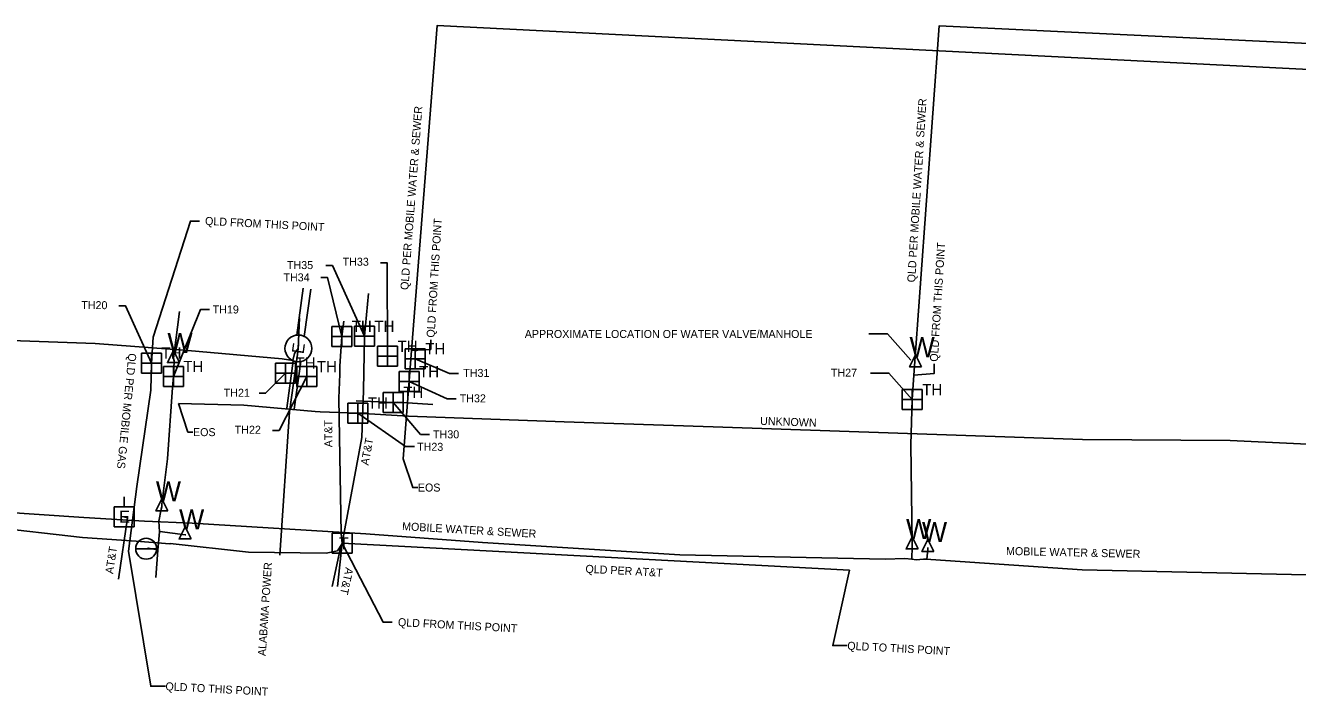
# Model space of a CAD drawing. Extents: x 1797765 to 1816938, y 246120 to 250965.
# Drawn here: x 1798766.8 to 1799084.8, y 248819.2 to 248986.7 of the extents above; entities that cross this region are included whole.
import ezdxf

# ---------------------------------------------------------------- set-up
doc = ezdxf.new("R2010")
doc.units = 0
for name, color, linetype in [('EX-OHUT-ELEC', 7, 'Continuous'), ('EX-UGUT-ELEC', 7, 'Continuous'), ('EX-UGUT-ELEC-X-CARDNO-X', 7, 'Continuous'), ('EX-UGUT-FOC-X-CARDNO-X', 7, 'Continuous'), ('EX-UGUT-GAS_MAIN-X-CARDNO-X', 7, 'Continuous'), ('EX-UGUT-PHONE', 7, 'Continuous'), ('EX-UGUT-TXT', 7, 'Continuous'), ('EX-UGUT-WATER', 7, 'Continuous'), ('EX-UGUT-WATER-X-CARDNO-X', 7, 'Continuous'), ('EX-UGUT-X-CARDNO-X', 7, 'Continuous'), ('SU_QLATestHole_ep', 7, 'Continuous'), ('UG-BURIED SANITARY SEWER', 7, 'Continuous'), ('UGUT-TXT', 7, 'Continuous')]:
    doc.layers.add(name, color=color, linetype=linetype)

msp = doc.modelspace()

# ---------------------------------------------------------------- linework, layer by layer
at = {"layer": 'EX-OHUT-ELEC'}
for p, q in [((1798791.5, 248868.94), (1798791.5, 248866.44)), ((1798789, 248866.44), (1798789, 248861.44)), ((1798794, 248861.44), (1798794, 248866.44)), ((1798789, 248861.44), (1798794, 248861.44))]:
    msp.add_line(p, q, dxfattribs=at)
msp.add_lwpolyline([(1798794, 248866.44), (1798791.5, 248866.44), (1798789, 248866.44)], dxfattribs=at)
at = {"layer": 'EX-UGUT-ELEC'}
for p, q in [((1798834.61, 248909.32), (1798836.23, 248921.06)), ((1798836.48, 248909.01), (1798838.11, 248920.8)), ((1798833.73, 248902.9), (1798832.11, 248891.11)), ((1798835.62, 248902.71), (1798833.99, 248890.85))]:
    msp.add_line(p, q, dxfattribs=at)
msp.add_circle((1798835.01, 248906), 3.35, dxfattribs=at)
at = {"layer": 'EX-UGUT-ELEC-X-CARDNO-X'}
for points in [[(1798735.14, 248908.97), (1798784.23, 248907.21), (1798807.35, 248905.49), (1798831, 248903.38), (1798833.59, 248902.99), (1798834.03, 248904.75), (1798834.95, 248906), (1798835.06, 248907.8), (1798835.33, 248913.62)], [(1798830.37, 248854.33), (1798832.78, 248890.14), (1798834.77, 248904.45), (1798834.95, 248906)]]:
    msp.add_lwpolyline(points, dxfattribs=at)
at = {"layer": 'EX-UGUT-FOC-X-CARDNO-X'}
msp.add_line((1798845.98, 248857.32), (1798972.76, 248850.58), dxfattribs=at)
for points in [[(1798844.81, 248846.5), (1798845.98, 248857.32), (1798850.89, 248883.71), (1798851.27, 248895.5), (1798851.53, 248909.03), (1798852.54, 248919.76)], [(1798845.98, 248857.32), (1798845.72, 248859.62), (1798845.15, 248893.61), (1798845.37, 248899.55), (1798845.4, 248901.59), (1798845.86, 248909.01), (1798846.34, 248912.82)], [(1798452.8, 248869.31), (1798454.41, 248875.69), (1798456.91, 248875.31), (1798485.69, 248873.18), (1798536.5, 248869.69), (1798574.45, 248870.48), (1798588.78, 248870.53), (1798685, 248864.35), (1798734.11, 248864.07), (1798781.01, 248858.73), (1798794.5, 248857.79), (1798802.91, 248857.14), (1798802.96, 248857.22), (1798822.56, 248855.06), (1798841.97, 248854.84), (1798844.79, 248855.44), (1798846.01, 248857.33), (1798845.98, 248857.32)], [(1798790.05, 248848.31), (1798792.3, 248863.69), (1798791.5, 248863.94)], [(1798845.98, 248857.32), (1798845.38, 248855.37), (1798843.49, 248846.47)]]:
    msp.add_lwpolyline(points, dxfattribs=at)
at = {"layer": 'EX-UGUT-GAS_MAIN-X-CARDNO-X'}
msp.add_lwpolyline([(1798792.53, 248855.29), (1798794.61, 248871.47), (1798798.13, 248895.56), (1798798.29, 248902.34), (1798798.73, 248908.82)], dxfattribs=at)
at = {"layer": 'EX-UGUT-PHONE'}
for p, q in [((1798848.48, 248859.82), (1798843.48, 248859.82)), ((1798843.48, 248859.82), (1798843.48, 248854.82)), ((1798848.48, 248854.82), (1798848.48, 248859.82)), ((1798843.48, 248854.82), (1798848.48, 248854.82))]:
    msp.add_line(p, q, dxfattribs=at)
at = {"layer": 'EX-UGUT-TXT'}
for points in [[(1798810.26, 248937.84), (1798808.01, 248937.84), (1798798.73, 248908.82)], [(1798841.9, 248926.74), (1798843.54, 248926.74), (1798851.53, 248909.03)], [(1798855.53, 248927.42), (1798857.17, 248927.42), (1798857.32, 248904.03)], [(1798840.65, 248923.77), (1798842.29, 248923.77), (1798845.86, 248909.01)], [(1798790.15, 248916.63), (1798791.8, 248916.63), (1798798.29, 248902.34)], [(1798812.83, 248915.76), (1798810.57, 248915.76), (1798803.76, 248899)], [(1798977.66, 248909.64), (1798982.25, 248909.64), (1798988.08, 248903.03)], [(1798868.11, 248908.17), (1798868.11, 248905.74), (1798863.32, 248905.48)], [(1798875.08, 248899.73), (1798872.82, 248899.73), (1798864.21, 248903.42)], [(1798825.17, 248894.79), (1798826.81, 248894.79), (1798831.81, 248899.85)], [(1798978.05, 248899.83), (1798982.64, 248899.83), (1798988.47, 248893.22)], [(1798993.93, 248902.13), (1798993.93, 248899.71), (1798988.9, 248899.32)], [(1798828.54, 248885.5), (1798830.19, 248885.5), (1798837.14, 248898.95)], [(1798874.48, 248893.42), (1798872.22, 248893.42), (1798862.69, 248897.7)], [(1798808.67, 248885.08), (1798807.39, 248885.08), (1798805.02, 248892.23)], [(1798867.81, 248884.53), (1798865.55, 248884.53), (1798858.73, 248892.53)], [(1798864.06, 248881.47), (1798861.8, 248881.47), (1798849.89, 248889.84)], [(1798864.88, 248871.23), (1798863.6, 248871.23), (1798861.24, 248878.38)], [(1798801.79, 248821.56), (1798798.12, 248821.56), (1798792.53, 248855.29)], [(1798858.49, 248837.55), (1798856.23, 248837.55), (1798845.98, 248857.32)], [(1798972.24, 248831.72), (1798968.58, 248831.72), (1798972.76, 248850.58)]]:
    msp.add_lwpolyline(points, dxfattribs=at)
at = {"layer": 'EX-UGUT-WATER'}
for p, q in [((1798805.27, 248902.45), (1798803.77, 248905.45)), ((1798990.8, 248901.4), (1798989.3, 248904.4)), ((1798802.38, 248865.4), (1798800.88, 248868.4)), ((1798808.19, 248858.37), (1798806.69, 248861.37)), ((1798989.94, 248855.91), (1798988.44, 248858.91)), ((1798993.9, 248855.23), (1798992.4, 248858.23)), ((1798794.33, 248855.94), (1798799.58, 248855.94))]:
    msp.add_line(p, q, dxfattribs=at)
for points in [[(1798803.77, 248905.45), (1798802.27, 248902.45), (1798805.27, 248902.45)], [(1798989.3, 248904.4), (1798987.8, 248901.4), (1798990.8, 248901.4)], [(1798800.88, 248868.4), (1798799.38, 248865.4), (1798802.38, 248865.4)], [(1798806.69, 248861.37), (1798805.19, 248858.37), (1798808.19, 248858.37)], [(1798988.44, 248858.91), (1798986.94, 248855.91), (1798989.94, 248855.91)], [(1798992.4, 248858.23), (1798990.9, 248855.23), (1798993.9, 248855.23)]]:
    msp.add_lwpolyline(points, dxfattribs=at)
msp.add_circle((1798796.96, 248855.94), 2.62, dxfattribs=at)
at = {"layer": 'EX-UGUT-WATER-X-CARDNO-X'}
for points in [[(1798988.9, 248899.32), (1798995.21, 248986.66), (1799521.08, 248961.5)], [(1798805.28, 248915.24), (1798803.9, 248904.18), (1798803.77, 248903.45), (1798803.95, 248902.9), (1798803.76, 248899), (1798803.57, 248896.25), (1798802.31, 248878.44), (1798800.88, 248867.11), (1798800.88, 248866.4), (1798800.72, 248865.81), (1798800.14, 248862.82), (1798800.29, 248860.2), (1798799.85, 248855.55), (1798799.36, 248848.73)], [(1798988.34, 248853.31), (1798988.47, 248856.53), (1798988.44, 248856.91), (1798988.48, 248857.39), (1798988.08, 248882.02), (1798988.47, 248893.22), (1798988.9, 248899.32)], [(1798685.79, 248870.12), (1798781.34, 248863.77), (1798796.52, 248862.81), (1798808.44, 248862.33), (1798851.84, 248859.62), (1798881.05, 248857.49), (1798930.39, 248854.37), (1798981.68, 248853.31), (1798986.59, 248853.5), (1798988.34, 248853.31), (1798989.48, 248853.2), (1798991.29, 248853.29), (1798992.11, 248853.31), (1798993.09, 248853.22), (1799030.93, 248850.68), (1799131.89, 248848.4)], [(1798800.29, 248860.2), (1798800.36, 248860.21), (1798806.69, 248859.37), (1798806.92, 248859.4)], [(1798799.85, 248855.56), (1798799.71, 248855.65), (1798797.52, 248856.07), (1798796.96, 248855.94)], [(1798992.11, 248853.31), (1798992.4, 248855.74), (1798992.4, 248856.23)]]:
    msp.add_lwpolyline(points, dxfattribs=at)
at = {"layer": 'EX-UGUT-X-CARDNO-X'}
for points in [[(1798805.02, 248892.23), (1798821.39, 248891.83), (1798839.2, 248890.25), (1798840.43, 248890.19), (1798849.89, 248889.84), (1798862.58, 248889.1), (1798901.44, 248887.68), (1798938.68, 248886.37), (1799031.01, 248883.21), (1799067.99, 248882.95), (1799152.4, 248879.01)], [(1798849.43, 248892.91), (1798858.73, 248892.53), (1798859.74, 248892.58), (1798868.62, 248891.95)]]:
    msp.add_lwpolyline(points, dxfattribs=at)
at = {"layer": 'SU_QLATestHole_ep'}
for p, q in [((1798843.36, 248911.51), (1798848.36, 248911.51)), ((1798843.36, 248906.51), (1798843.36, 248911.51)), ((1798843.36, 248911.51), (1798843.36, 248909.01)), ((1798845.86, 248911.51), (1798843.36, 248911.51)), ((1798843.36, 248909.01), (1798848.36, 248909.01)), ((1798843.36, 248909.01), (1798845.86, 248909.01)), ((1798845.86, 248911.51), (1798845.86, 248906.51)), ((1798845.86, 248909.01), (1798845.86, 248911.51)), ((1798848.36, 248909.01), (1798845.86, 248909.01)), ((1798845.86, 248909.01), (1798845.86, 248906.51)), ((1798848.36, 248911.51), (1798848.36, 248906.51)), ((1798848.36, 248906.51), (1798848.36, 248909.01)), ((1798849.03, 248911.53), (1798854.03, 248911.53)), ((1798849.03, 248906.53), (1798849.03, 248911.53)), ((1798849.03, 248911.53), (1798849.03, 248909.03)), ((1798851.53, 248911.53), (1798849.03, 248911.53)), ((1798849.03, 248909.03), (1798854.03, 248909.03)), ((1798849.03, 248909.03), (1798851.53, 248909.03)), ((1798851.53, 248911.53), (1798851.53, 248906.53)), ((1798851.53, 248909.03), (1798851.53, 248911.53)), ((1798854.03, 248909.03), (1798851.53, 248909.03)), ((1798851.53, 248909.03), (1798851.53, 248906.53)), ((1798854.03, 248911.53), (1798854.03, 248906.53)), ((1798854.03, 248906.53), (1798854.03, 248909.03)), ((1798848.36, 248906.51), (1798843.36, 248906.51)), ((1798845.86, 248906.51), (1798848.36, 248906.51)), ((1798854.03, 248906.53), (1798849.03, 248906.53)), ((1798851.53, 248906.53), (1798854.03, 248906.53)), ((1798854.82, 248906.53), (1798859.82, 248906.53)), ((1798854.82, 248901.53), (1798854.82, 248906.53)), ((1798854.82, 248906.53), (1798854.82, 248904.03)), ((1798857.32, 248906.53), (1798854.82, 248906.53)), ((1798857.32, 248906.53), (1798857.32, 248901.53)), ((1798857.32, 248904.03), (1798857.32, 248906.53)), ((1798859.82, 248906.53), (1798859.82, 248901.53)), ((1798861.71, 248905.92), (1798866.71, 248905.92)), ((1798861.71, 248900.92), (1798861.71, 248905.92)), ((1798861.71, 248905.92), (1798861.71, 248903.42)), ((1798864.21, 248905.92), (1798861.71, 248905.92)), ((1798864.21, 248905.92), (1798864.21, 248900.92)), ((1798864.21, 248903.42), (1798864.21, 248905.92)), ((1798866.71, 248905.92), (1798866.71, 248900.92)), ((1798795.79, 248904.84), (1798800.79, 248904.84)), ((1798795.79, 248899.84), (1798795.79, 248904.84)), ((1798795.79, 248904.84), (1798795.79, 248902.34)), ((1798798.29, 248904.84), (1798795.79, 248904.84)), ((1798798.29, 248904.84), (1798798.29, 248899.84)), ((1798798.29, 248902.34), (1798798.29, 248904.84)), ((1798800.79, 248904.84), (1798800.79, 248899.84)), ((1798854.82, 248904.03), (1798859.82, 248904.03)), ((1798854.82, 248904.03), (1798857.32, 248904.03)), ((1798859.82, 248904.03), (1798857.32, 248904.03)), ((1798857.32, 248904.03), (1798857.32, 248901.53)), ((1798859.82, 248901.53), (1798859.82, 248904.03)), ((1798861.71, 248903.42), (1798866.71, 248903.42)), ((1798861.71, 248903.42), (1798864.21, 248903.42)), ((1798866.71, 248903.42), (1798864.21, 248903.42)), ((1798864.21, 248903.42), (1798864.21, 248900.92)), ((1798866.71, 248900.92), (1798866.71, 248903.42)), ((1798795.79, 248902.34), (1798800.79, 248902.34)), ((1798795.79, 248902.34), (1798798.29, 248902.34)), ((1798800.79, 248899.84), (1798795.79, 248899.84)), ((1798800.79, 248902.34), (1798798.29, 248902.34)), ((1798798.29, 248902.34), (1798798.29, 248899.84)), ((1798798.29, 248899.84), (1798800.79, 248899.84)), ((1798800.79, 248899.84), (1798800.79, 248902.34)), ((1798801.26, 248901.5), (1798806.26, 248901.5)), ((1798801.26, 248896.5), (1798801.26, 248901.5)), ((1798801.26, 248901.5), (1798801.26, 248899)), ((1798803.76, 248901.5), (1798801.26, 248901.5)), ((1798803.76, 248901.5), (1798803.76, 248896.5)), ((1798803.76, 248899), (1798803.76, 248901.5)), ((1798806.26, 248901.5), (1798806.26, 248896.5)), ((1798829.31, 248902.35), (1798834.31, 248902.35)), ((1798829.31, 248897.35), (1798829.31, 248902.35)), ((1798829.31, 248902.35), (1798829.31, 248899.85)), ((1798831.81, 248902.35), (1798829.31, 248902.35)), ((1798829.31, 248899.85), (1798834.31, 248899.85)), ((1798829.31, 248899.85), (1798831.81, 248899.85)), ((1798831.81, 248902.35), (1798831.81, 248897.35)), ((1798831.81, 248899.85), (1798831.81, 248902.35)), ((1798834.31, 248899.85), (1798831.81, 248899.85)), ((1798831.81, 248899.85), (1798831.81, 248897.35)), ((1798834.31, 248902.35), (1798834.31, 248897.35)), ((1798834.31, 248897.35), (1798834.31, 248899.85)), ((1798834.64, 248901.45), (1798839.64, 248901.45)), ((1798834.64, 248896.45), (1798834.64, 248901.45)), ((1798834.64, 248901.45), (1798834.64, 248898.95)), ((1798837.14, 248901.45), (1798834.64, 248901.45)), ((1798837.14, 248901.45), (1798837.14, 248896.45)), ((1798837.14, 248898.95), (1798837.14, 248901.45)), ((1798839.64, 248901.45), (1798839.64, 248896.45)), ((1798859.82, 248901.53), (1798854.82, 248901.53)), ((1798857.32, 248901.53), (1798859.82, 248901.53)), ((1798860.19, 248900.2), (1798865.19, 248900.2)), ((1798860.19, 248895.2), (1798860.19, 248900.2)), ((1798860.19, 248900.2), (1798860.19, 248897.7)), ((1798862.69, 248900.2), (1798860.19, 248900.2)), ((1798866.71, 248900.92), (1798861.71, 248900.92)), ((1798862.69, 248900.2), (1798862.69, 248895.2)), ((1798862.69, 248897.7), (1798862.69, 248900.2)), ((1798864.21, 248900.92), (1798866.71, 248900.92)), ((1798865.19, 248900.2), (1798865.19, 248895.2)), ((1798801.26, 248899), (1798806.26, 248899)), ((1798801.26, 248899), (1798803.76, 248899)), ((1798806.26, 248896.5), (1798801.26, 248896.5)), ((1798806.26, 248899), (1798803.76, 248899)), ((1798803.76, 248899), (1798803.76, 248896.5)), ((1798803.76, 248896.5), (1798806.26, 248896.5)), ((1798806.26, 248896.5), (1798806.26, 248899)), ((1798834.31, 248897.35), (1798829.31, 248897.35)), ((1798831.81, 248897.35), (1798834.31, 248897.35)), ((1798834.64, 248898.95), (1798839.64, 248898.95)), ((1798834.64, 248898.95), (1798837.14, 248898.95)), ((1798839.64, 248896.45), (1798834.64, 248896.45)), ((1798839.64, 248898.95), (1798837.14, 248898.95)), ((1798837.14, 248898.95), (1798837.14, 248896.45)), ((1798837.14, 248896.45), (1798839.64, 248896.45)), ((1798839.64, 248896.45), (1798839.64, 248898.95)), ((1798860.19, 248897.7), (1798865.19, 248897.7)), ((1798860.19, 248897.7), (1798862.69, 248897.7)), ((1798865.19, 248897.7), (1798862.69, 248897.7)), ((1798862.69, 248897.7), (1798862.69, 248895.2)), ((1798865.19, 248895.2), (1798865.19, 248897.7)), ((1798856.23, 248895.03), (1798861.23, 248895.03)), ((1798856.23, 248890.03), (1798856.23, 248895.03)), ((1798856.23, 248895.03), (1798856.23, 248892.53)), ((1798858.73, 248895.03), (1798856.23, 248895.03)), ((1798858.73, 248895.03), (1798858.73, 248890.03)), ((1798858.73, 248892.53), (1798858.73, 248895.03)), ((1798865.19, 248895.2), (1798860.19, 248895.2)), ((1798861.23, 248895.03), (1798861.23, 248890.03)), ((1798862.69, 248895.2), (1798865.19, 248895.2)), ((1798985.97, 248895.72), (1798990.97, 248895.72)), ((1798985.97, 248890.72), (1798985.97, 248895.72)), ((1798985.97, 248895.72), (1798985.97, 248893.22)), ((1798988.47, 248895.72), (1798985.97, 248895.72)), ((1798985.97, 248893.22), (1798990.97, 248893.22)), ((1798985.97, 248893.22), (1798988.47, 248893.22)), ((1798988.47, 248895.72), (1798988.47, 248890.72)), ((1798988.47, 248893.22), (1798988.47, 248895.72)), ((1798990.97, 248893.22), (1798988.47, 248893.22)), ((1798988.47, 248893.22), (1798988.47, 248890.72)), ((1798990.97, 248895.72), (1798990.97, 248890.72)), ((1798990.97, 248890.72), (1798990.97, 248893.22)), ((1798847.39, 248892.34), (1798852.39, 248892.34)), ((1798847.39, 248887.34), (1798847.39, 248892.34)), ((1798847.39, 248892.34), (1798847.39, 248889.84)), ((1798849.89, 248892.34), (1798847.39, 248892.34)), ((1798849.89, 248892.34), (1798849.89, 248887.34)), ((1798849.89, 248889.84), (1798849.89, 248892.34)), ((1798852.39, 248892.34), (1798852.39, 248887.34)), ((1798856.23, 248892.53), (1798861.23, 248892.53)), ((1798856.23, 248892.53), (1798858.73, 248892.53)), ((1798861.23, 248890.03), (1798856.23, 248890.03)), ((1798861.23, 248892.53), (1798858.73, 248892.53)), ((1798858.73, 248892.53), (1798858.73, 248890.03)), ((1798858.73, 248890.03), (1798861.23, 248890.03)), ((1798861.23, 248890.03), (1798861.23, 248892.53)), ((1798990.97, 248890.72), (1798985.97, 248890.72)), ((1798988.47, 248890.72), (1798990.97, 248890.72)), ((1798847.39, 248889.84), (1798852.39, 248889.84)), ((1798847.39, 248889.84), (1798849.89, 248889.84)), ((1798852.39, 248887.34), (1798847.39, 248887.34)), ((1798852.39, 248889.84), (1798849.89, 248889.84)), ((1798849.89, 248889.84), (1798849.89, 248887.34)), ((1798849.89, 248887.34), (1798852.39, 248887.34)), ((1798852.39, 248887.34), (1798852.39, 248889.84))]:
    msp.add_line(p, q, dxfattribs=at)
at = {"layer": 'UG-BURIED SANITARY SEWER'}
msp.add_line((1798861.24, 248878.38), (1798863.32, 248905.48), dxfattribs=at)
msp.add_lwpolyline([(1798863.32, 248905.48), (1798869.73, 248986.74), (1799520.3, 248953.93)], dxfattribs=at)

# ---------------------------------------------------------------- texts
at = {"layer": 'EX-OHUT-ELEC'}
msp.add_text('E', height=3, dxfattribs=at).set_placement((1798790.21, 248862.44))
at = {"layer": 'EX-UGUT-ELEC'}
msp.add_text('E', height=3, rotation=82.1717, dxfattribs=at).set_placement((1798836.32, 248904.52))
at = {"layer": 'EX-UGUT-PHONE'}
msp.add_text('T', height=3, dxfattribs=at).set_placement((1798845.16, 248855.82))
at = {"layer": 'EX-UGUT-TXT'}
for s, rotation, p in [('QLD PER MOBILE WATER & SEWER', 85.6003, (1798862.49, 248920.57)), ('QLD PER MOBILE WATER & SEWER', 86.4501, (1798989.2, 248922.46)), ('QLD FROM THIS POINT', 356.9533, (1798811.64, 248936.91)), ('QLD FROM THIS POINT', 86.4501, (1798869.04, 248908.66)), ('QLD FROM THIS POINT', 86.4501, (1798994.86, 248902.63)), ('QLD PER MOBILE GAS', 264.274, (1798792.55, 248904.87)), ('AT&T', 90.5037, (1798843.53, 248881.3)), ('UNKNOWN', 358.0379, (1798950.42, 248886.91)), ('AT&T', 79.4512, (1798852.52, 248876.68)), ('MOBILE WATER & SEWER', 356.7056, (1798860.9, 248860.6)), ('AT&T', 81.6706, (1798788.7, 248849.55)), ('MOBILE WATER & SEWER', 358.7034, (1799011.9, 248854.4)), ('ALABAMA POWER', 86.1414, (1798826.85, 248829.06)), ('QLD PER AT&T', 356.9573, (1798906.73, 248849.95)), ('AT&T', 257.9862, (1798846.83, 248851.39)), ('QLD FROM THIS POINT', 356.9533, (1798859.86, 248836.62)), ('QLD TO THIS POINT', 356.9533, (1798972.19, 248830.72)), ('QLD TO THIS POINT', 356.9533, (1798801.74, 248820.57))]:
    msp.add_text(s, height=2, rotation=rotation, dxfattribs=at).set_placement(p)
for s, p in [('TH33', (1798846.08, 248926.67)), ('TH35', (1798832.16, 248925.84)), ('TH34', (1798831.28, 248922.76)), ('TH20', (1798780.74, 248915.82)), ('TH19', (1798813.59, 248914.74)), ('TH31', (1798876.22, 248898.88)), ('TH27', (1798968.14, 248898.95)), ('TH21', (1798816.35, 248893.91)), ('TH32', (1798875.35, 248892.52)), ('EOS', (1798808.67, 248884.08)), ('TH22', (1798819.1, 248884.68)), ('TH30', (1798868.68, 248883.54)), ('TH23', (1798864.69, 248880.41)), ('EOS', (1798864.88, 248870.23))]:
    msp.add_text(s, height=2, dxfattribs=at).set_placement(p)
at = {"layer": 'EX-UGUT-WATER'}
for p in [(1798802.27, 248904.86), (1798987.79, 248903.82), (1798799.37, 248867.81), (1798805.18, 248860.78), (1798986.93, 248858.33), (1798990.89, 248857.65)]:
    msp.add_text('W', height=5, dxfattribs=at).set_placement(p)
at = {"layer": 'SU_QLATestHole_ep'}
for p in [(1798848.36, 248910.11), (1798854.03, 248910.13), (1798800.79, 248903.44), (1798859.82, 248905.13), (1798866.71, 248904.52), (1798806.26, 248900.1), (1798834.31, 248900.95), (1798839.64, 248900.05), (1798865.19, 248898.8), (1798861.23, 248893.63), (1798990.97, 248894.32), (1798852.39, 248890.94)]:
    msp.add_text('TH', height=2.8, dxfattribs=at).set_placement(p)
at = {"layer": 'UGUT-TXT'}
msp.add_text('APPROXIMATE LOCATION OF WATER VALVE/MANHOLE', height=2, dxfattribs=at).set_placement((1798891.61, 248908.62))

doc.saveas('drawing.dxf')
